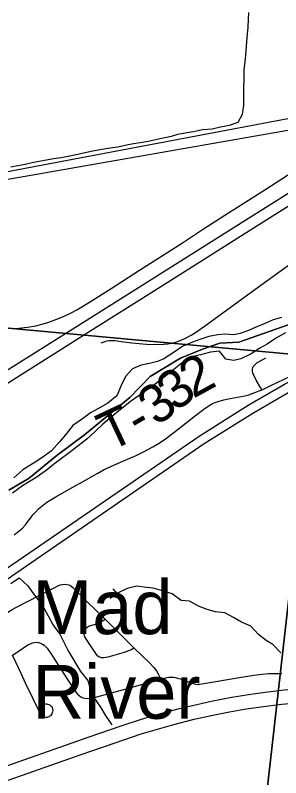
# Model space of a CAD drawing. Extents: x 0 to 1134, y 0 to 440.
# Drawn here: x 841.236 to 841.626, y 360.746 to 361.864 of the extents above; entities that cross this region are included whole.
import ezdxf

# ---------------------------------------------------------------- set-up
doc = ezdxf.new("R2010")
doc.units = 0
for name, color, linetype in [('GM_X_County_Road', 7, 'Continuous'), ('GM_X_Interstate_Route', 7, 'Continuous'), ('GM_X_Major_River', 7, 'Continuous'), ('GM_X_Minor_River', 7, 'Continuous'), ('GM_X_Rail_Line', 7, 'Continuous'), ('GM_X_Section', 7, 'Continuous'), ('GM_X_State_Route', 7, 'Continuous'), ('GM_X_Township', 7, 'Continuous'), ('GM_X_Township_Road', 7, 'Continuous'), ('GM_X_Township_Road_Text', 7, 'Continuous'), ('GM_X_Unincorporated_Text', 7, 'Continuous')]:
    doc.layers.add(name, color=color, linetype=linetype)

msp = doc.modelspace()

# ---------------------------------------------------------------- linework, layer by layer
at = {"layer": 'GM_X_County_Road'}
for points in [[(841.2327, 361.4043), (841.2419, 361.4049), (841.2542, 361.4065), (841.2664, 361.4087), (841.2754, 361.4108), (841.2843, 361.4134), (841.2959, 361.4176), (841.3074, 361.4224), (841.3186, 361.4277), (841.3268, 361.432), (841.3454, 361.4431), (841.377, 361.463), (841.4187, 361.49), (841.4815, 361.5302), (841.5111, 361.5495), (841.5436, 361.5708), (841.6039, 361.609), (841.651, 361.6393)], [(841.3626, 361.3835), (841.3682, 361.3855), (841.371, 361.3863), (841.3739, 361.3868), (841.3769, 361.3871), (841.3798, 361.3871), (841.3828, 361.3869), (841.3919, 361.3854), (841.4075, 361.3837), (841.4291, 361.3818), (841.4415, 361.3813), (841.4539, 361.3815), (841.46, 361.382), (841.466, 361.383), (841.4719, 361.3847), (841.4807, 361.3877), (841.4863, 361.3902), (841.4944, 361.3946), (841.5022, 361.3996), (841.5174, 361.4103), (841.5876, 361.4617), (841.6934, 361.5381)]]:
    msp.add_lwpolyline(points, dxfattribs=at)
at = {"layer": 'GM_X_Interstate_Route'}
for points in [[(841.216, 360.7603), (841.3449, 360.8058), (841.3919, 360.822), (841.4215, 360.8315), (841.4482, 360.8395), (841.4752, 360.8468), (841.4963, 360.852), (841.5236, 360.8579), (841.554, 360.8638), (841.5785, 360.8679), (841.6031, 360.8714), (841.6308, 360.8747), (841.6587, 360.8773), (841.6834, 360.879), (841.7082, 360.8802), (841.7361, 360.8808), (841.761, 360.8808), (841.7889, 360.88), (841.816, 360.8786), (841.8497, 360.876), (841.9282, 360.8692), (842.1437, 360.8501)], [(841.1922, 360.7305), (841.3329, 360.7798), (841.3828, 360.7972), (841.4211, 360.81), (841.4449, 360.8173), (841.4688, 360.824), (841.499, 360.8316), (841.5262, 360.8378), (841.5506, 360.8427), (841.5721, 360.8465), (841.5967, 360.85), (841.6275, 360.8537), (841.6554, 360.8564), (841.6778, 360.8582), (841.7034, 360.8596), (841.735, 360.8606), (841.759, 360.8606), (841.7871, 360.8598), (841.8157, 360.8582), (841.8448, 360.8558), (841.9036, 360.8508), (842.0026, 360.8423), (842.1404, 360.8296), (842.1444, 360.8292)]]:
    msp.add_lwpolyline(points, dxfattribs=at)
at = {"layer": 'GM_X_Major_River'}
for points in [[(841.627, 361.4206), (841.6148, 361.4174), (841.6017, 361.4112), (841.5883, 361.4058), (841.5787, 361.4018), (841.5664, 361.3972), (841.5565, 361.3951), (841.5436, 361.3962), (841.5337, 361.3952), (841.5203, 361.3929), (841.5073, 361.3886), (841.4962, 361.3847), (841.4823, 361.3785), (841.468, 361.3689), (841.4545, 361.3601), (841.4449, 361.3561), (841.4331, 361.353), (841.4212, 361.3509), (841.4086, 361.3455), (841.398, 361.334), (841.392, 361.3208), (841.3852, 361.3057), (841.3721, 361.2953), (841.3574, 361.2869), (841.3466, 361.2811), (841.335, 361.2722), (841.3211, 361.2622), (841.3102, 361.2488), (841.3016, 361.2387), (841.2898, 361.2253), (841.279, 361.2172), (841.2682, 361.2102), (841.2578, 361.2039), (841.2474, 361.1973), (841.2342, 361.1854)], [(841.6326, 361.398), (841.6195, 361.3907), (841.606, 361.3818), (841.5952, 361.3756), (841.5825, 361.3675), (841.5675, 361.3603), (841.5571, 361.3574), (841.5454, 361.3596), (841.5358, 361.3712), (841.5228, 361.37), (841.5083, 361.3661), (841.4949, 361.363), (841.481, 361.3542), (841.469, 361.3446), (841.4547, 361.3331), (841.4438, 361.3246), (841.4326, 361.3165), (841.423, 361.3098), (841.4071, 361.2984), (841.3909, 361.2858), (841.3777, 361.2751), (841.3649, 361.2643), (841.3536, 361.2535), (841.3416, 361.2424), (841.3288, 361.2324), (841.3153, 361.2221), (841.3025, 361.2125), (841.2924, 361.2051), (841.2816, 361.1962), (841.2669, 361.1862), (841.2469, 361.1738), (841.2325, 361.163)]]:
    msp.add_lwpolyline(points, dxfattribs=at)
at = {"layer": 'GM_X_Minor_River'}
for points in [[(841.2299, 361.6414), (841.2402, 361.6436), (841.2512, 361.6457), (841.2631, 361.6483), (841.2771, 361.6511), (841.2924, 361.654), (841.3038, 361.6554), (841.3167, 361.6575), (841.3282, 361.6604), (841.3407, 361.6633), (841.3529, 361.6654), (841.364, 361.6675), (841.375, 361.6693), (841.3868, 361.6711), (841.3994, 361.674), (841.41, 361.6757), (841.4233, 361.6778), (841.434, 361.6796), (841.4511, 361.6836), (841.4656, 361.6868), (841.4751, 361.6894), (841.4881, 361.6919), (841.498, 361.6933), (841.5113, 361.6965), (841.525, 361.6975), (841.5376, 361.7004), (841.5505, 361.7029), (841.5635, 361.7073), (841.5697, 361.719), (841.5718, 361.7319), (841.5716, 361.7459), (841.5717, 361.7566), (841.5723, 361.7718), (841.5724, 361.7843), (841.5737, 361.7957), (841.5746, 361.8059), (841.5755, 361.818), (841.5764, 361.8313), (841.5781, 361.8465), (841.5783, 361.8583), (841.5788, 361.8681)], [(841.23, 361.0305), (841.2422, 361.0391), (841.255, 361.0271), (841.2617, 361.0176), (841.27, 361.0068), (841.2793, 360.9931), (841.2845, 360.9831), (841.2919, 360.9697), (841.3016, 360.9563), (841.309, 360.9418), (841.3139, 360.9319), (841.3198, 360.9223), (841.3261, 360.9112), (841.3321, 360.9017), (841.343, 360.8886), (841.3466, 360.8753), (841.3529, 360.8619), (841.3615, 360.8493), (841.3693, 360.8363), (841.3779, 360.8233)], [(841.6261, 360.9289), (841.6144, 360.9412), (841.6046, 360.947), (841.593, 360.9559), (841.5821, 360.9682), (841.5685, 360.974), (841.5564, 360.9806), (841.544, 360.9876), (841.5299, 360.9893), (841.5178, 360.9925), (841.505, 360.9972), (841.4918, 361.0049), (841.48, 361.0055), (841.4668, 361.0155), (841.4525, 361.0198), (841.4388, 361.0238), (841.429, 361.0247), (841.4149, 361.0267), (841.4005, 361.0231), (841.3875, 361.0172), (841.3756, 361.0086)], [(841.3858, 361.016), (841.3799, 361.023)]]:
    msp.add_lwpolyline(points, dxfattribs=at)
at = {"layer": 'GM_X_Rail_Line'}
for points in [[(841.7289, 361.7267), (841.636, 361.7122), (841.1421, 361.6188), (840.658, 361.5251), (840.1995, 361.4383), (839.8708, 361.3715), (839.4959, 361.2977), (839.3695, 361.2741), (839.2837, 361.2579), (839.1515, 361.2347), (839.0452, 361.2426), (838.9712, 361.2584), (838.8788, 361.2852), (838.7922, 361.3241), (838.7273, 361.3639), (838.6544, 361.4226), (838.4388, 361.6154), (838.1628, 361.8666)], [(836.2484, 359.8987), (836.4737, 360.0545), (836.8961, 360.3143), (837.1477, 360.5217), (837.2503, 360.5989), (837.3703, 360.682), (837.4559, 360.737), (837.6488, 360.8541), (837.8041, 360.9469), (837.8854, 360.994), (838.2343, 361.1415), (838.6187, 361.2463), (838.9046, 361.2586), (838.9722, 361.246), (839.0457, 361.2318), (839.1496, 361.2259), (839.2509, 361.2446), (839.3511, 361.2632), (839.494, 361.2889), (839.8268, 361.3583), (841.1445, 361.6094), (841.7312, 361.712), (841.7847, 361.7229)], [(841.2157, 361.0472), (841.5064, 361.2469), (841.5781, 361.2919), (841.6312, 361.3227), (841.6738, 361.3456), (841.7175, 361.3666), (841.7685, 361.3888), (841.8955, 361.4414), (842.0247, 361.4947), (842.1416, 361.5429), (842.2366, 361.5815), (842.2657, 361.5916), (842.2929, 361.5999), (842.3425, 361.614), (842.3784, 361.626), (842.4072, 361.6364), (842.4457, 361.6526)], [(840.6063, 360.6113), (840.745, 360.7068), (840.8262, 360.7629), (840.9346, 360.8379), (841.0901, 360.9447), (841.2233, 361.0362), (841.5137, 361.2358), (841.585, 361.2805), (841.6377, 361.3111), (841.6798, 361.3337), (841.7231, 361.3545), (841.7738, 361.3765), (841.9006, 361.4291), (842.0298, 361.4824), (842.1467, 361.5306), (842.3784, 361.626)]]:
    msp.add_lwpolyline(points, dxfattribs=at)
at = {"layer": 'GM_X_Section'}
for points in [[(840.7489, 362.4766), (841.77, 362.3661), (841.678, 361.3633), (840.6525, 361.4576)], [(840.6525, 361.4576), (841.678, 361.3633), (841.5643, 360.3612), (840.5521, 360.4549)], [(841.678, 361.3633), (842.6377, 361.2776), (842.5486, 360.2705), (841.5643, 360.3612)]]:
    msp.add_lwpolyline(points, close=True, dxfattribs=at)
at = {"layer": 'GM_X_State_Route'}
for points in [[(841.2222, 361.3419), (841.3378, 361.4149), (841.5245, 361.5323), (841.5823, 361.5687), (841.6375, 361.6036), (841.7268, 361.6598), (841.7794, 361.693), (841.8319, 361.7262), (841.8793, 361.7558), (841.9712, 361.8138), (842.0027, 361.8336), (842.0212, 361.8452), (842.0403, 361.8572), (842.0607, 361.87)], [(840.7541, 361.0286), (840.7645, 361.0352), (840.8492, 361.0885), (840.9253, 361.1362), (841.012, 361.1901), (841.0892, 361.2385), (841.1768, 361.2939), (841.2662, 361.3501), (841.3565, 361.4073), (841.4181, 361.4459), (841.5003, 361.4981), (841.5908, 361.555), (841.6884, 361.6167), (841.7786, 361.6735), (841.8737, 361.7332), (841.96, 361.7879), (842.0138, 361.8216)]]:
    msp.add_lwpolyline(points, dxfattribs=at)
at = {"layer": 'GM_X_Township'}
for points in [[(841.2271, 361.1673), (841.2567, 361.185), (841.2981, 361.219), (841.3381, 361.2486), (841.4047, 361.3033), (841.4342, 361.3344), (841.4786, 361.361), (841.5112, 361.3743), (841.5363, 361.3832), (841.5644, 361.3847), (841.6828, 361.4261)], [(841.6828, 361.4261), (841.5644, 361.3847), (841.5363, 361.3832), (841.5112, 361.3743), (841.4786, 361.361), (841.4342, 361.3344), (841.4047, 361.3033), (841.3381, 361.2486), (841.2981, 361.219), (841.2567, 361.185), (841.2271, 361.1673)]]:
    msp.add_lwpolyline(points, dxfattribs=at)
at = {"layer": 'GM_X_Township_Road'}
for points in [[(841.598, 361.3146), (841.5994, 361.3151), (841.6105, 361.3203), (841.6718, 361.3499), (841.6772, 361.353), (841.68, 361.3548), (841.6825, 361.3565), (841.6871, 361.3606), (841.6922, 361.3639), (841.6975, 361.3669), (841.703, 361.3697), (841.72, 361.3772), (841.7521, 361.3908), (841.7558, 361.3922), (841.7594, 361.393), (841.7609, 361.3932), (841.762, 361.3932), (841.763, 361.3929)], [(841.598, 361.3146), (841.596, 361.3181), (841.5898, 361.3289), (841.5863, 361.336), (841.5857, 361.3376), (841.5851, 361.339), (841.5845, 361.3412), (841.5842, 361.343), (841.5844, 361.3456), (841.5848, 361.3472), (841.5854, 361.3487), (841.5862, 361.3499), (841.5877, 361.3515), (841.5909, 361.354), (841.5959, 361.3572), (841.6041, 361.3616)], [(841.2348, 361.1022), (841.2422, 361.1078), (841.247, 361.1118), (841.2513, 361.1165), (841.255, 361.1214), (841.2587, 361.1264), (841.2624, 361.1313), (841.2664, 361.1359), (841.2707, 361.1403), (841.2754, 361.1442), (841.2828, 361.1497), (841.295, 361.1571), (841.3166, 361.1694), (841.3393, 361.1822), (841.3497, 361.188), (841.3576, 361.1923), (841.3669, 361.1976), (841.3765, 361.2022), (841.3907, 361.2084), (841.4136, 361.2181), (841.4247, 361.2236), (841.4384, 361.2311), (841.449, 361.2376), (841.4567, 361.2429), (841.4692, 361.2521), (841.5008, 361.2772), (841.5131, 361.2865), (841.5209, 361.2916), (841.5259, 361.2944), (841.5283, 361.2954), (841.5339, 361.2975), (841.5425, 361.3), (841.5516, 361.302), (841.573, 361.3058), (841.5791, 361.3074), (841.5879, 361.3105), (841.598, 361.3146)], [(841.2093, 360.9782), (841.2125, 360.9805), (841.2229, 360.9872), (841.2327, 360.9929), (841.2374, 360.9954), (841.2723, 361.0136), (841.2944, 361.025), (841.3, 361.0276), (841.3029, 361.0287), (841.3059, 361.0294), (841.309, 361.0295), (841.312, 361.0293), (841.3148, 361.0285), (841.3179, 361.0271), (841.3208, 361.0248), (841.3249, 361.0211), (841.336, 361.0102), (841.3425, 361.0035), (841.3668, 360.9796), (841.3681, 360.9783)], [(841.411, 360.9358), (841.4091, 360.9349), (841.4064, 360.9335), (841.4026, 360.9318), (841.396, 360.9295), (841.3722, 360.9227), (841.3692, 360.922), (841.3662, 360.9217), (841.3631, 360.9218), (841.3601, 360.9226), (841.3575, 360.9243), (841.3555, 360.9266), (841.3417, 360.947), (841.3385, 360.9523), (841.3374, 360.9552), (841.3372, 360.9583), (841.3377, 360.9613), (841.3391, 360.9641), (841.3412, 360.9663), (841.3438, 360.9679), (841.3471, 360.9689), (841.3525, 360.9705), (841.3571, 360.9717), (841.3601, 360.973), (841.3622, 360.9742), (841.3661, 360.9769), (841.3681, 360.9783)], [(841.3681, 360.9783), (841.389, 360.9578), (841.4088, 360.938), (841.411, 360.9358)], [(841.2326, 360.9256), (841.2422, 360.9321), (841.2503, 360.9377), (841.256, 360.941), (841.2589, 360.9424), (841.2618, 360.9435), (841.2647, 360.9442), (841.2677, 360.9444), (841.2706, 360.9441), (841.2736, 360.9432), (841.2764, 360.9418), (841.2789, 360.94), (841.2813, 360.938), (841.2833, 360.9356), (841.2886, 360.928), (841.3119, 360.8912), (841.3223, 360.8757), (841.3259, 360.8707), (841.3279, 360.8683), (841.3302, 360.8662), (841.3327, 360.8644), (841.3356, 360.8631), (841.3386, 360.8624), (841.3417, 360.8621), (841.3448, 360.8623), (841.3509, 360.8632), (841.3989, 360.8761), (841.4494, 360.8905)], [(841.411, 360.9358), (841.4331, 360.9141), (841.4395, 360.9073), (841.4434, 360.9024), (841.4467, 360.8972), (841.4481, 360.8942), (841.4494, 360.8905)], [(841.2749, 360.8526), (841.2765, 360.8532), (841.2783, 360.8536), (841.2806, 360.854), (841.2822, 360.854), (841.2836, 360.8539), (841.2858, 360.8532), (841.2868, 360.8527), (841.2878, 360.8521), (841.2892, 360.8508), (841.2905, 360.8488), (841.2911, 360.8467), (841.2914, 360.8445), (841.2913, 360.8427), (841.2908, 360.8409), (841.2902, 360.8393), (841.2891, 360.838), (841.288, 360.8367), (841.2868, 360.8359), (841.2857, 360.8352), (841.2842, 360.8347), (841.2827, 360.8344), (841.2811, 360.8344), (841.2796, 360.8346), (841.278, 360.8352), (841.2768, 360.8359), (841.2746, 360.838), (841.2728, 360.8406), (841.2713, 360.8433), (841.262, 360.8623), (841.2517, 360.8845), (841.2451, 360.8985), (841.2372, 360.9153), (841.2326, 360.9256)], [(841.4494, 360.8905), (841.4567, 360.8923), (841.4615, 360.8931), (841.465, 360.8933), (841.4686, 360.8931), (841.4716, 360.8927), (841.4745, 360.892), (841.4803, 360.8902), (841.4889, 360.8868), (841.4977, 360.8838), (841.5008, 360.883), (841.504, 360.8827), (841.5071, 360.8829), (841.5103, 360.8833), (841.5651, 360.8929), (841.5864, 360.8964), (841.5986, 360.8979), (841.6078, 360.8986), (841.6174, 360.8989), (841.6275, 360.8989)]]:
    msp.add_lwpolyline(points, dxfattribs=at)

# ---------------------------------------------------------------- texts
at = {"layer": 'GM_X_Township_Road_Text'}
for s, rotation, p in [('2', 28.7131, (841.4974, 361.3013)), ('3', 37.6033, (841.4719, 361.2814)), ('3', 37.5476, (841.4443, 361.2602)), ('T', 25.222, (841.3746, 361.2236)), ('-', 30.2569, (841.4178, 361.2442))]:
    msp.add_text(s, height=0.0568, rotation=rotation, dxfattribs=at).set_placement(p)
at = {"layer": 'GM_X_Unincorporated_Text'}
for s, p in [('Mad', (841.2615, 360.9564)), ('River', (841.2615, 360.8323))]:
    msp.add_text(s, height=0.07898, rotation=0, dxfattribs=at).set_placement(p)

doc.saveas('drawing.dxf')
